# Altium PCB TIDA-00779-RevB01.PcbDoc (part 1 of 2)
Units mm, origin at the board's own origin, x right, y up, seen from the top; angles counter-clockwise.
Board outline 215 x 145 mm, 2 copper layers (Top Layer, Bottom Layer), stack 1.575 mm thick; 136 components, 56 nets, 280 pads, 32 vias.
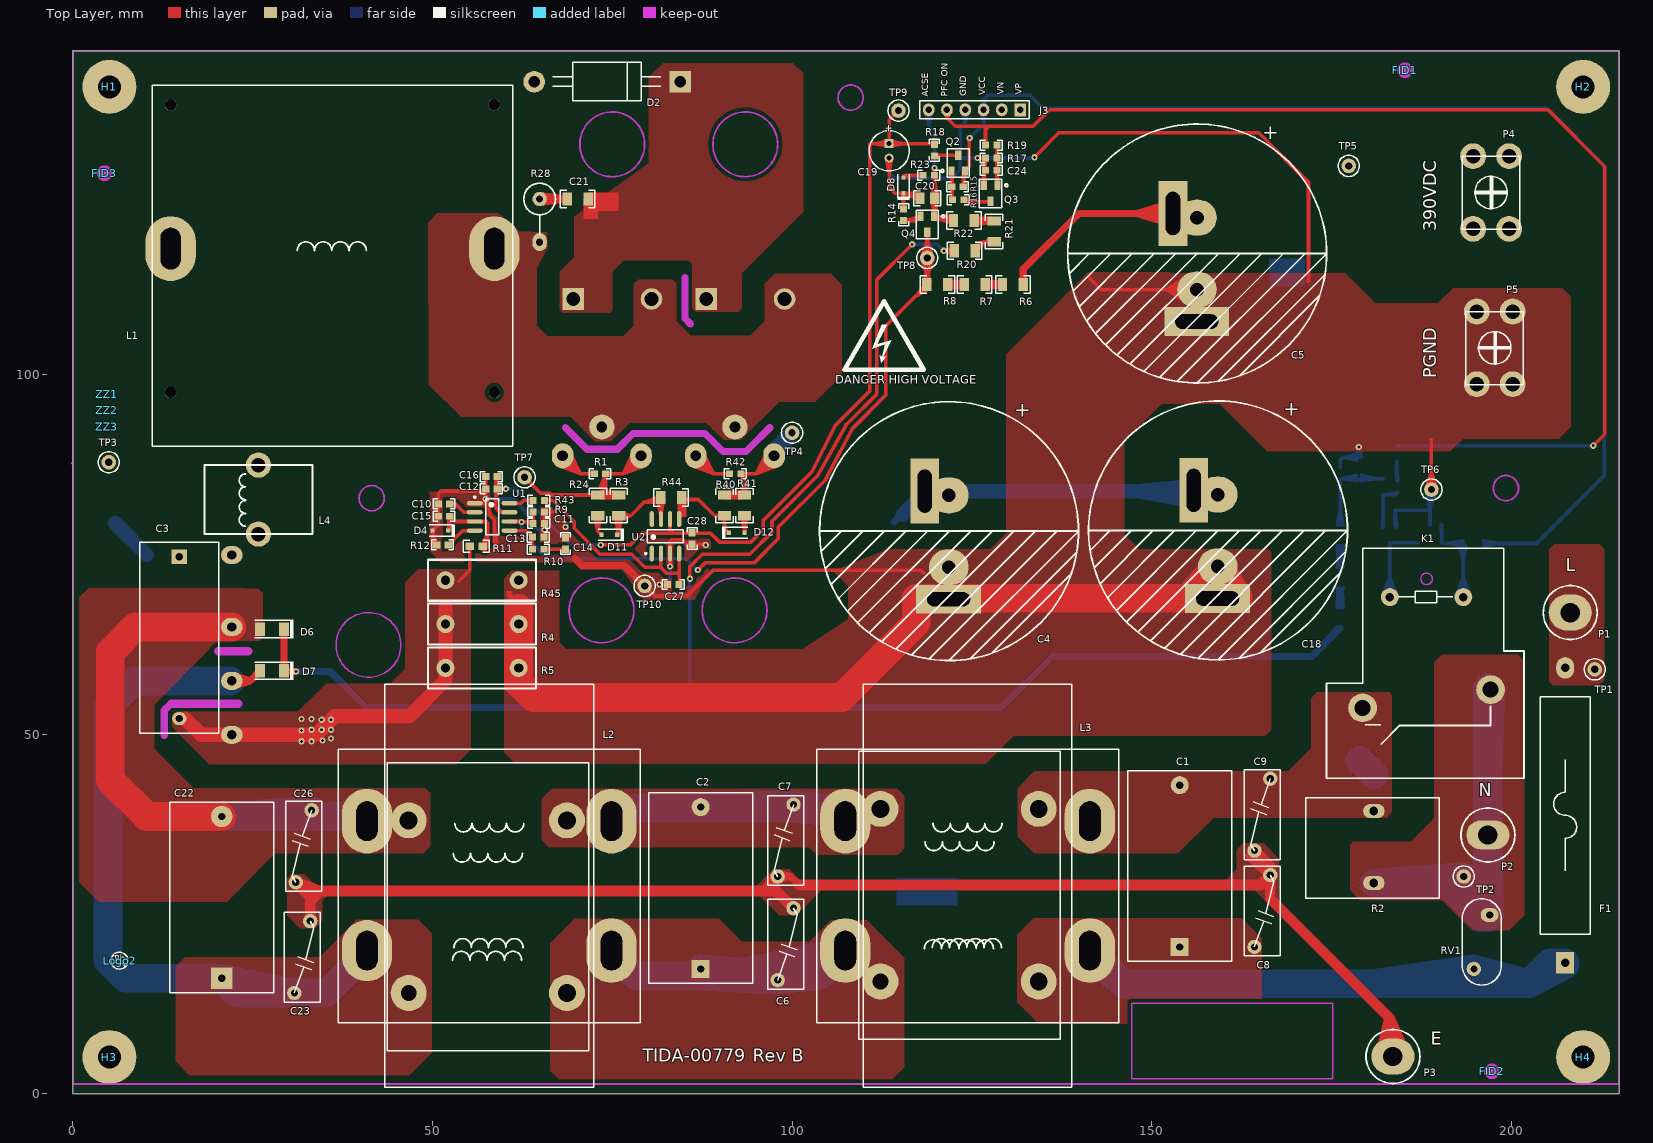
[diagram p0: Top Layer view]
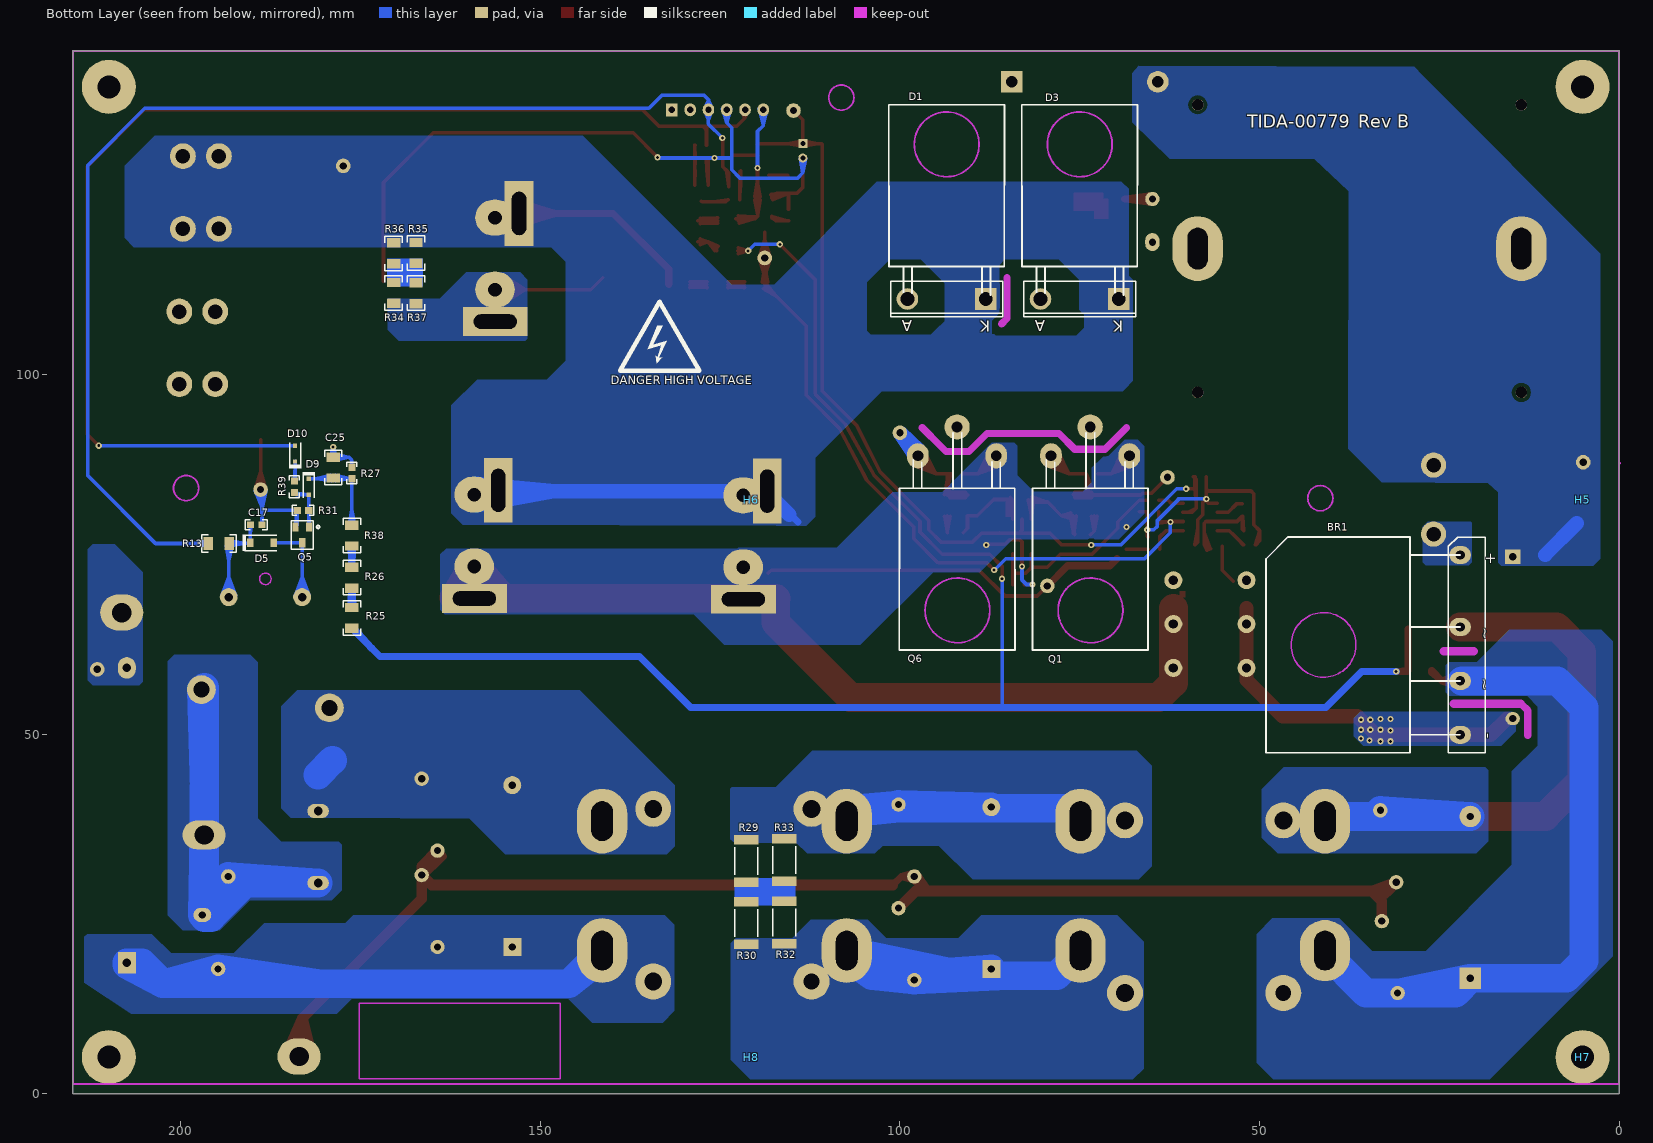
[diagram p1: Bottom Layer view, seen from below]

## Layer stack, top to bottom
Top Solder: solder mask 0.0102, Solder Resist, Dk 3.5
Top Layer: signal copper 0.0356
Dielectric1: core 1.5037, FR-4, Dk 4.8
Bottom Layer: signal copper 0.0356
Bottom Solder: solder mask 0.0102, Solder Resist, Dk 3.5

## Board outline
0,0 215,0 215,145 0,145

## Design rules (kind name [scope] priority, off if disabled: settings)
AcuteAngle [All] p1: minimum=4.50000000000000E+0001 checktracksonly=FALSE
AssemblyTestPointUsage [All] p1: valid=2
Clearance Clearance_BoardEdge_MountingHoles [OnCopper and InComponentClass('Mounting Holes') vs IsKeepOut] p1: gap=0.3
Clearance Clearance_BoardEdge_Poly [OnCopper and InPoly vs IsKeepOut] p2 off: gap=0.25
Clearance Clearance_BoardEdge [OnCopper and Not InComponentClass('Logo') and not InComponentClass('FiducialMark') and not InRegion(1000,500,4000,800) and Not IsKeepout vs IsKeepOut] p3 off: gap=1.905
Clearance Clearance_Poly [InPolygon] p4: gap=0.5
Clearance [All] p5: gap=0.25
ComponentClearance ComponentClearance_MountingHoles_FiducialMarks [InComponentClass('Mounting Holes') vs InComponentClass('FiducialMark')] p1 off: gap=1.27 collisioncheckmode=3 verticalgap=0.254 showdistances=FALSE
ComponentClearance ComponentClearance_Shunt [InComponentClass('Header') vs InComponentClass('Shunt')] p2 off: gap=0 collisioncheckmode=3 verticalgap=0 showdistances=FALSE
ComponentClearance ComponentClearance_Logo [InComponentClass('Logo')] p3 off: gap=1.27 collisioncheckmode=3 verticalgap=0.254 showdistances=FALSE
ComponentClearance ComponentClearance_ScrewToNut [(HasFootprint('NY PMS 440 0025 PH')) vs (HasFootprint('Keystone_1902C'))] p4 off: gap=0.127 collisioncheckmode=3 verticalgap=0.254 showdistances=FALSE
ComponentClearance ComponentClearance_MountingHoles [InComponentClass('Mounting Holes')] p5 off: gap=6.35 collisioncheckmode=3 verticalgap=2540 showdistances=FALSE
ComponentClearance ComponentClearance_SmallPassives [HasFootprint('0201*') or HasFootprint('0402*') or HasFootprint('0508') or HasFootprint('0603*') or HasFootprint('0612') or HasFootprint('0805*') or HasFootprint('0815*') or HasFootprint('0830*') or HasFootprint('1206*') or HasFootprint('1210*') or HasFootprint('1808*') or HasFootprint('1812*') or HasFootprint('1825*') or HasFootprint('2010*') or HasFootprint('2220*') or HasFootprint('2225*') or HasFootprint('2512*') or HasFootprint('2728*') or HasFootprint('3518*') vs HasFootprint('0201*') or HasFootprint('0402*') or HasFootprint('0508') or HasFootprint('0603*') or HasFootprint('0612') or HasFootprint('0805*') or HasFootprint('0815*') or HasFootprint('0830*') or HasFootprint('1206*') or HasFootprint('1210*') or HasFootprint('1808*') or HasFootprint('1812*') or HasFootprint('1825*') or HasFootprint('2010*') or HasFootprint('2220*') or HasFootprint('2225*') or HasFootprint('2512*') or HasFootprint('2728*') or HasFootprint('3518*')] p6 off: gap=0.508 collisioncheckmode=3 verticalgap=0.254 showdistances=FALSE
ComponentClearance ComponentClearance_THtoSMT [IsThruComponent vs IsSMTComponent] p7 off: gap=2.54 collisioncheckmode=3 verticalgap=0.762 showdistances=FALSE
ComponentClearance ComponentClearance_THtoTH [IsThruComponent vs IsThruComponent] p8 off: gap=3 collisioncheckmode=3 verticalgap=0.762 showdistances=FALSE
ComponentClearance [All] p9 off: gap=1.016 collisioncheckmode=3 verticalgap=0.254 showdistances=FALSE
DiffPairsRouting [All] p1: maxlimit=2.54 minlimit=0.254 mostfreqgap=0.254 toplayer_minwidth=0.381 toplayer_maxwidth=0.381 toplayer_prefwidth=0.381 bottomlayer_minwidth=0.381 bottomlayer_maxwidth=0.381 bottomlayer_prefwidth=0.381 maxuncoupledlength=25.4
FabricationTestPointUsage TestPointUsage [All] p1: valid=2 allowmultiple=FALSE
FabricationTestpoint Testpoint [All] p1: side=3 testpointundercomponent=TRUE minsize=1.016 maxsize=2.54 preferedsize=1.524 minholesize=0 maxholesize=1.016 preferedholesize=0.813 testpointgrid=0.025 allowsidetop=TRUE allowsidebottom=TRUE usegrid=TRUE gridtolerance=0
FanoutControl Fanout_LCC [IsLCC] p1: bgadir=Out bgaviamode=Centered fanoutstyle=Auto fanoutdirection=Alternating viagrid=0.025 // Fanout_LCC (Default Rule)
FanoutControl Fanout_BGA [IsBGA] p2: bgadir=Out bgaviamode=Centered fanoutstyle=Auto fanoutdirection=Alternating viagrid=0.025 // Fanout_BGA (Default Rule)
FanoutControl Fanout_Default [All] p4: bgadir=Out bgaviamode=Centered fanoutstyle=Auto fanoutdirection=Alternating viagrid=0.025 // Fanout_Default (Default Rule)
FanoutControl Fanout_Small [(CompPinCount < 5)] p5: bgadir=Out bgaviamode=Centered fanoutstyle=Auto fanoutdirection=OutThenIn viagrid=0.025 // Fanout_Small (Default Rule)
HoleSize [All] p1: absolutevalues=TRUE maxlimit=6.375 minlimit=0.203 maxpercent=80.000 minpercent=20.000
MinimumAnnularRing MinimumAnnularRing_ThermalPadVias [IsVia and InAnyComponent] p1: minimumring=0.15
MinimumAnnularRing [All] p2: minimumring=0.229
MinimumSolderMaskSliver MinimumSolderMaskSliver_Logo [InComponentClass('Logo') vs InComponentClass('Logo')] p1: minsoldermaskwidth=0.018
MinimumSolderMaskSliver [All] p2: minsoldermaskwidth=0.1
PlaneConnect [All] p1: planeconnectstyle=Relief reliefexpansion=0.254 reliefentries=4 reliefconductorwidth=0.254 reliefairgap=0.254
PolygonConnect [All] p1: connectstyle=Direct reliefconductorwidth=0.254 reliefentries=4 polygonreliefangle="90 Angle" airgapwidth=0.254
RoutingVias ThermalPadVias [IsVia and InAnyComponent] p1: holewidth=0.2 width=0.5 viastyle="Through Hole" minholewidth=0.2 minwidth=0.5 maxholewidth=0.33 maxwidth=0.6
RoutingVias [All] p2: holewidth=0.406 width=0.864 viastyle="Through Hole" minholewidth=0.2 minwidth=0.66 maxholewidth=1.016 maxwidth=1.651
SilkToSilkClearance SilkToSilkClearance_Pb-FreeLogo [(HasFootprint('Pb-Free_Overlay_Medium') OR HasFootprint('Pb-Free_Overlay_Small')) vs (HasFootprint('Pb-Free_Overlay_Medium') OR HasFootprint('Pb-Free_Overlay_Small'))] p1: silktosilkclearance=0
SilkToSilkClearance [All] p2: silktosilkclearance=0.102
SilkToSolderMaskClearance "Silk to Solder Mask Opening" [IsPad] p1: minsilkscreentomaskgap=0.102 clearancetoexposedcopper=TRUE
SolderMaskExpansion [All] p1: expansion=0.05
UnpouredPolygon [All] p1: allowunpoured=FALSE
Width [All] p1: maxlimit=10 minlimit=0.152 preferedwidth=0.254 checkconnectedcopper=TRUE
15 further rules are at their usual default settings.

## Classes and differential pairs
component class TIDA-00779-RevA02: BR1 C1 C2 C3 C4 C5 C6 C7 C8 C9 C10 C11 C12 C13 C14 C15 C16 C17 C18 C19 C20 C21 C22 C23 C24 C25 C26 C27 C28 D1 D2 D3 D4 D5 D6 D7 D8 D9 D10 D11 D12 F1 HS1 K1 L1 L2 L3 P1 P2 P3 P4 P5 Q1 Q2 Q3 Q4 Q5 Q6 R1 R2 R3 R4 R5 R6 R7 R8 R9 R10 R11 R12 R13 R14 R15 R16 R17 R18 R19 R20 R21 R22 R23 R24 R25 R26 R27 R28 R29 R30 R31 R32 R33 R34 R35 R36 R37 R38 R39 R40 R41 R42 R43 R44 RV1 S1 TP1 TP2 TP3 TP4 TP5 TP6 TP7 TP8 TP9 TP10 U1 U2

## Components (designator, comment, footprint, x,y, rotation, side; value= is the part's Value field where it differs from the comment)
BR1 "GBJ3508" BRIDGE-GBJ1510-BV 22.1,62.4 r270 bottom
C1 "B32923C3225K" B32923_29.5mm#1 153.9,31.65 r90 top
C2 "B32923C3225K" B32923_29.5mm#1 87.3,28.6 r90 top
C3 "B32923C3474K" B32923_20.5mm 14.8,63.4 r270 top
C4 "LGG2W681MELC50" E/P10/D36/E2 120.125,76.269 r0 top
C5 "LGG2W681MELC50" E/P10/D36/E2 154.625,114.869 r0 top
C6 "2.2nF" C/10/12/5 99.1,20.8 r90 top
C7 "2.2nF" C/10/12/5 99.1,35.2 r270 top
C8 "2.2nF" C/10/12/5 165.4,25.4 r90 top
C9 "2.2nF" C/10/12/5 165.4,38.8 r270 top
C10 "GRM188R71H472KA01D" 0603 51.6,82 r180 top
C11 "C0603C821K5RACTU" 0603 64.8,79.3 r0 top
C12 "C0603C105K3RACTU" 0603 58.2,84.1 r180 top
C13 "C0603C394K4RACTU" 0603 64.7,77.4 r0 top
C14 "0603ZD475KAT2A" 0603 68.5,76.5 r90 top
C15 "06031C272JAT2A" 0603 51.6,80.3 r180 top
C16 "0603YC104JAT2A" 0603 58.2,85.8 r180 top
C17 "C1608X7R1E105K080AB" 0603 189.5,79.1 r180 bottom
C18 "LGG2W681MELC50" E/P10/D36/E2 157.525,76.369 r0 top
C19 "UPW1V100MDD6" PW_500x700 113.5,131.1 r270 top
C20 "C2012X5R1E106K125AB" 0805_HV 118.816,124.5 r180 top
C21 "1206AC102KAT1A" 1206 70.2,124.4 r180 top
C22 "B32923C3225K" B32923_29.5mm#2 20.7,27.3 r90 top
C23 "2.2nF" C/10/12/5 31.9,19 r90 top
C24 "C0603C474K4RACTU" 0603 127.7,128.4 r180 top
C25 "UMK316BBJ106ML-T" 1206 178.8,87.05 r90 bottom
C26 "2.2nF" C/10/12/5 32.1,34.4 r270 top
C27 "C1608X7R1H221K" 0603 83.5,70.8 r180 top
C28 "UMK107AB7105KA-T" 0603 86.1,77.2 r90 top
D1 "FFH30S60S" TO247BV-D 93.5,110.5 r0 bottom
D2 "1N5406" DO-201AD 74.3,140.7 r180 top
D3 "FFH30S60S" TO247BV-D 75,110.5 r0 bottom
D4 "BAT54HT1G" sod-323 51.1,78.3 r180 top
D5 "1N4148W-7-F" SOD-123 188.7,76.6 r180 bottom
D6 "CGRM4007-G" MINI-SMA 27.7,64.6 r180 top
D7 "CGRM4007-G" MINI-SMA 27.7,58.8 r180 top
D8 "BAT54HT1G" sod-323 115.5,126.3 r90 top
D9 "BZX384-C12,115" sod-323 182.2,84.4 r270 bottom
D10 "BAT54HT1G" sod-323 184.1,89 r90 bottom
D11 "MMDL914-TP" sod-323 74.6,77.7 r180 top
D12 "MMDL914-TP" sod-323 92.3,78 r0 top
"DANGER HIGH VOLTAGE" "Comment" IEC_HighVoltage_Medium 112.8,105.1 r0 top
"DANGER HIGH VOLTAGE" "Comment" IEC_HighVoltage_Medium 133.4,105 r180 bottom
F1 "40A" Fuse-6*32 207.5,38.7 r270 top
FID1 "Fiducial" Fiducial10-20 185.2,142.3 r0 top
FID2 "Fiducial" Fiducial10-20 197.3,3.1 r0 top
FID3 "Fiducial" Fiducial10-20 4.4,128 r0 top
H1 "NY PMS 440 0025 PH" "NY PMS 440 0025 PH"#1 5.08,82.55 r0 top locked
H2 "NY PMS 440 0025 PH" "NY PMS 440 0025 PH"#2 120.65,82.55 r0 top locked
H3 "NY PMS 440 0025 PH" "NY PMS 440 0025 PH"#3 5.08,5.08 r0 top locked
H4 "NY PMS 440 0025 PH" "NY PMS 440 0025 PH"#4 120.65,5.08 r0 top locked
H5 "1902C" Keystone_1902C 5.08,82.55 r180 bottom locked
H6 "1902C" Keystone_1902C 120.65,82.55 r180 bottom locked
H7 "1902C" Keystone_1902C 5.08,5.08 r180 bottom locked
H8 "1902C" Keystone_1902C 120.65,5.08 r180 bottom locked
J3 "PEC06SAAN" HDR1X6 131.7,136.8 r180 top
K1 "HF105F-1/12DT-1HS" RY-SLA-S112DM 185.9,56.8 r180 top (schematic designator RY1)
L1 "" L4p-55*50P40*45 36.1,117.5 r270 top
L2 "2.5 mH" L4P-56*42P42*38-LT38-4P#1 57.9,28.9 r90 top
L3 "2.5 mH" L4P-56*42P42*38-LT38-4P#2 124.4,28.9 r90 top
L4 "" L-15*9 25.8,82.6 r90 top
Logo2 "Pb-Free Symbol" Pb-Free_Overlay_Small 6.5,18.5 r0 top
P1 "" P-CONNECT#1 208.551,66.725 r0 top
P2 "" P-CONNECT#2 197.1,35.8 r0 top
P3 "" P-CONNECT#1 183.9,5 r0 top
P4 "PCB-7(M4)" PCB-7(M4) 197.2,125.3 r270 top (schematic designator P8)
P5 "PCB-7(M4)" PCB-7(M4) 197.7,103.7 r270 top (schematic designator P8)
Q1 "IPW60R099P6" TO-247BV2 73.5,67.2 r0 bottom
Q2 "MMBT3906" SOT23-3p 123.1,129.4 r0 top
Q3 "2N7002-7-F" SOT23-3p 127.6,125.2 r180 top
Q4 "BC847CLT1G" SOT23-3p 118.8,120.9 r180 top
Q5 "2N7002-7-F" SOT23-3p 183.1,77.7 r0 bottom
Q6 "IPW60R099P6" TO-247BV2 92,67.2 r0 bottom
R1 "CRCW060310K0FKEA" 0603 73.3,86.2 r180 top
R2 "B470N" PTC-18*13P10 180.9,34.3 r180 top
R3 "CRCW120622R0JNEA" 1206 75.9,81.8 r90 top
R4 "" R/P10/5W 56.9,65.3 r180 top
R5 "" R/P10/5W 56.9,59.2 r180 top
R6 "CRCW1206332KFKEA" 1206 130.7,112.5 r0 top
R7 "CRCW1206332KFKEA" 1206 125.4,112.5 r0 top
R8 "CRCW1206340KFKEA" 1206 120.2,112.5 r0 top
R9 "CRCW060313K0FKEA" 0603 64.8,80.9 r180 top
R10 "RT0603DRE0718K7L" 0603 64.7,75.7 r0 top
R11 "CRCW0603221RFKEA" 0603M 56.1,76.1 r0 top
R12 "RT0603DRE0747KL" 0603 51.4,76.3 r0 top
R13 "CRCW1206100RFKEA" 1206 194.7,76.5 r180 bottom
R14 "CRCW060313K7FKEA" 0603 115.5,122.2 r90 top
R15 "CRCW060310K0FKEA" 0603 123,126.1 r180 top
R16 "CRCW06036K80JNEA" 0603 123.1,124.3 r180 top
R17 "CRCW06036K80JNEA" 0603 127.7,130.1 r0 top
R18 "CRCW060315R4FKEA" 0603 119.8,131.2 r90 top
R19 "CRCW060310K0FKEA" 0603 127.7,131.9 r0 top
R20 "CRCW1206332KFKEA" 1206 124,117.2 r180 top
R21 "CRCW1206332KFKEA" 1206 128.1,119.9 r90 top
R22 "CRCW1206340KFKEA" 1206 123.9,121.4 r0 top
R23 "CRCW060310K0FKEA" 0603 119,127.7 r180 top
R24 "CRCW12064R70JNEA" 1206 73,81.8 r90 top
R25 "CRCW1206340KFKEA" 1206 176.2,66.15 r270 bottom
R26 "CRCW1206340KFKEA" 1206 176.2,71.75 r90 bottom
R27 "CRCW0603221KFKEA" 0603 176.2,86.3 r270 bottom
R28 "CRM2512-FX-43R2ELF" R5/D4.4V 64.9,124.4 r270 top
R29 "CRCW251262K0JNEG" 2512 121.4,32.35 r270 bottom
R30 "CRCW251262K0JNEG" 2512 121.4,23.75 r270 bottom
R31 "CRCW060347K5FKEA" 0603 183,81.1 r180 bottom
R32 "CRCW251262K0JNEG" 2512 116.1,23.8 r270 bottom
R33 "CRCW251262K0JNEG" 2512 116.1,32.5 r270 bottom
R34 "CRCW1206221KFKEA" 1206 170.4,111.35 r90 bottom
R35 "CRCW1206221KFKEA" 1206 167.3,116.9 r90 bottom
R36 "CRCW1206221KFKEA" 1206 170.4,116.85 r90 bottom
R37 "CRCW1206221KFKEA" 1206 167.3,111.3 r90 bottom
R38 "CRCW120621K0FKEA" 1206 176.2,77.6 r90 bottom
R39 "CRCW06031K00FKEA" 0603 184.2,84.4 r270 bottom
R40 "CRCW120622R0JNEA" 1206 90.6,81.8 r90 top
R41 "CRCW12064R70JNEA" 1206 93.4,81.8 r90 top
R42 "CRCW060310K0FKEA" 0603 92.1,86.2 r180 top
R43 "RT0603DRE07100RL" 0603 64.8,82.5 r0 top
R44 "RC1206JR-070RL" 1206 83.2,82.9 r0 top
R45 "" R/P10/5W 56.9,71.4 r180 top (schematic designator R4)
RV1 "S10K275E2" VAR_S10K275E2 195.9,21.1 r270 top
TP1 "5000" Keystone5000 211.6,59 r0 top
TP2 "5000" Keystone5000 193.4,30.2 r0 top
TP3 "5000" Keystone5000 5,87.8 r0 top
TP4 "5000" Keystone5000 100,91.9 r0 top
TP5 "5000" Keystone5000 177.4,129 r0 top
TP6 "5001" Keystone5001 188.9,84 r0 top
TP7 "5000" Keystone5000 62.8,85.7 r0 top
TP8 "5000" Keystone5000 118.8,116.2 r0 top
TP9 "5000" Keystone5000 114.8,136.7 r0 top
TP10 "5001" Keystone5001 79.5,70.6 r0 top
U1 "UCC28180D" D0008A_N 58.3,80.2 r0 top
U2 "UCC27524AD" D0008A_N 82.4,77.5 r90 top
ZZ1 "These assemblies are ESD sensitive, ESD precautions shall be observed." AssemblyNote 4.699,97.259 r0 top
ZZ2 "These assemblies must be clean and free from flux and all contaminants. Use of no clean flux is not acceptable." AssemblyNote 4.699,95.01 r0 top
ZZ3 "These assemblies must comply with workmanship standards IPC-A-610 Class 2, unless otherwise specified." AssemblyNote 4.699,92.761 r0 top
? "Comment" "L4p-32*28 P22*24" 123.3,27.6 r90 top
? "Comment" "L4p-32*28 P22*24" 57.7,26 r90 top

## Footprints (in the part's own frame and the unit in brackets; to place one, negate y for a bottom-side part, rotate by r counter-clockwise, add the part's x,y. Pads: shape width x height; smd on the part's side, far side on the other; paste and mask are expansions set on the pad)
0603 [mm] "0603 from SM-752 data"
  rect 1x0.95 smd: 1(-0.8,0) 2(0.8,0)
  silkscreen extent -1.52,-0.69 1.52,0.69, body extent -0.87,-0.47 0.87,0.47, height 0.85
0603M [mm] "0603 from SM-752 data"
  rect 1.2x1.05 smd: 1(-0.9,0) 2(0.9,0)
  silkscreen extent -1.82,-0.84 1.82,0.84, body extent -0.87,-0.47 0.87,0.47, height 0.85
0805_HV [mil] "0805 with 30mil clearance between pads"
  rect 50x63 smd: 1(-40,0) 2(40,0)
  silkscreen extent -74,-40 74,40, body extent -43,-29 43,29, height 57
1206 [mm] "1206 from SM-752 data"
  rect 1.3x1.85 smd: 1(-1.45,0) 2(1.45,0)
  silkscreen extent -2.4,-1.21 2.4,1.21, body extent -1.7,-0.9 1.7,0.9, height 1.35
2512 [mm] "Chip Resistor, Body 6.3x3.2mm, IPC Medium Density"
  rect 1.3x3.4 smd: 1(-2.95,0) 2(2.95,0)
  silkscreen extent -1.9,-1.6 1.9,1.6, body extent -3.22,-1.67 3.22,1.67, height 0.71
AssemblyNote [mm] "Assembly Note"
B32923_20.5mm [mm] "Epcos film capacitors, 22.5mm spacing"
  rect 2x2.2 hole 1: 1(-11.25,0)
  oval 1.8x2 hole 1: 2(11.25,0)
  silkscreen extent -13.25,-5.5 13.25,5.5, body extent -13.25,-5.5 13.25,5.5, height 20.5
B32923_29.5mm#1 [mm] "Epcos film capacitors, 22.5mm spacing"
  rect 2.5x2.5 hole 1: 1(-11.25,0)
  round 2.5 hole 1: 2(11.25,0)
  silkscreen extent -13.25,-7.25 13.25,7.25, body extent -13.25,-7.25 13.25,7.25, height 29.5
B32923_29.5mm#2 [mm] "Epcos film capacitors, 22.5mm spacing"
  rect 3x3 hole 1: 1(-11.25,0)
  round 3 hole 1: 2(11.25,0)
  silkscreen extent -13.25,-7.25 13.25,7.25, body extent -13.25,-7.25 13.25,7.25, height 29.5
BRIDGE-GBJ1510-BV [mm]
  oval 2.5x3 hole 1.3: 1(-12.5,0) 2(-2.5,0) 3(5,0) 4(12.5,0)
  Keep-Out Layer circle w0.2: c0,-19 r4.5
  silkscreen extent -15,-27 15,3.5
C/10/12/5 [mm]
  round 2 hole 1: 1(-5,1.1) 2(5,-1.1)
  silkscreen extent -6.25,-2.5 6.25,2.5
D0008A_N [mm] "SOIC, 8-Leads, Body 4.9x3.9mm, Pitch 1.27mm, IPC Medium Density"
  oval 2.2x0.6 smd: 1(-2.4,1.905) 2(-2.4,0.635) 3(-2.4,-0.635) 4(-2.4,-1.905) 5(2.4,-1.905) 6(2.4,-0.635) 7(2.4,0.635) 8(2.4,1.905)
  silkscreen extent -2.52,-2.5 0.9,2.88, body extent -2,-2.5 2,2.5, height 1.75
DO-201AD [mm] "Vishay dimensions"
  rect 3x3 hole 1.6: 1(-10.16,0)
  round 3 hole 1.6: 2(10.16,0)
  silkscreen extent -7.47,-2.7 7.57,2.61, body extent -10.82,-2.74 10.82,2.61, height 5.33
E/P10/D36/E2 [mm]
  rect 4x9 hole 2 slot 6 at 90 deg: 1(-1.675,7.519)
  oval 5.5x5 hole 1.9: 1(1.675,6.931) 2(1.675,-3.069)
  rect 9x4 hole 2 slot 6 at 0 deg: 2(1.641,-7.519)
  silkscreen extent -16.29,-16.05 19.7,19.95
Fiducial10-20 [mm]
  round 1 smd mask+0.5: 1(0,0)
  Top Layer keep-out circle w1.178: c0,0 r0.5
Fuse-6*32 [mm]
  rect 3x2.5 hole 1.2: 1(20.5,0)
  oval 3x2.5 hole 1.2: 2(-20.5,0)
  silkscreen extent -16.5,-3.5 16.5,3.5
HDR1X6 [mm] "Connector; Header; 6 Position"
  rect 1.6x1.8 hole 0.9: 1(0,0)
  oval 1.6x1.8 hole 0.9: 2(2.54,0) 3(5.08,0) 4(7.62,0) 5(10.16,0) 6(12.7,0)
  silkscreen extent -1.27,-1.27 13.97,1.27
IEC_HighVoltage_Medium [mm]
  silkscreen extent -5.51,-4.46 5.51,5.09
Keystone5000 [mil] "For Keystone 500x miniature loop terminals"
  round 80 hole 40: 1(0,0)
  silkscreen extent -58,-58 58,58, body extent -49,-49 49,49, height 182
Keystone5001 [mil] "For Keystone 500x miniature loop terminals"
  round 80 hole 40: 1(0,0)
  silkscreen extent -58,-58 58,58, body extent -49,-49 49,49, height 182
Keystone_1902C [mm] "Hex Standoff, 4-40 threaded, nylon"
  body extent -3.68,-3.2 3.71,3.2, height 12.73
"L4p-32*28 P22*24" [mm]
  round 5 hole 2.5: 1(-12,-11) 3(12,11) 4(12,-11)
  round 5 hole 2.2: 2(-12,11)
  silkscreen extent -20,-14 20,14
L4p-55*50P40*45 [mm]
  oval 9x7 hole 2.8 slot 5.8 at 0 deg: 1(0,-22.5) 2(0,22.5)
  round 1.6 hole 1.6 unplated: 3(-20,22.5) 3(-20,-22.5) 3(20,22.5) 3(20,-22.5)
  silkscreen extent -22.75,-25.05 27.5,25.05
L4P-56*42P42*38-LT38-4P#1 [mm]
  oval 9x7 hole 3 slot 5.5 at 0 deg: 1(-9,-17) 3(9,17) 4(9,-17)
  oval 8.5x7 hole 3 slot 5.5 at 0 deg: 2(-9,17)
  silkscreen extent -28,-21 28,21
L4P-56*42P42*38-LT38-4P#2 [mm]
  oval 9x7 hole 3 slot 5.5 at 0 deg: 1(-9,-17) 2(-9,17) 3(9,17) 4(9,-17)
  silkscreen extent -28,-21 28,21
L-15*9 [mm]
  round 3.5 hole 2: 1(-4.8,0) 2(4.8,0)
  silkscreen extent -4.8,-7.5 4.8,7.5
MINI-SMA [mm] "COMCHIP"
  rect 1.4x1.9 smd: 1(-1.65,0) 2(1.65,0)
  silkscreen extent -3,-1.3 2.4,1.3, body extent -1.95,-0.9 1.95,0.9, height 1.7
"NY PMS 440 0025 PH"#1 [mm] "4-40 nylon screw and mounting hole"
  round 7.5 hole 3.2: 1(0,57.45)
  body extent -3.3,-3.3 3.3,3.3, height 2.69
"NY PMS 440 0025 PH"#2 [mm] "4-40 nylon screw and mounting hole"
  round 7.5 hole 3.2: 1(89.35,57.45)
  body extent -3.3,-3.3 3.3,3.3, height 2.69
"NY PMS 440 0025 PH"#3 [mm] "4-40 nylon screw and mounting hole"
  round 7.5 hole 3.2: 1(0,0)
  body extent -3.3,-3.3 3.3,3.3, height 2.69
"NY PMS 440 0025 PH"#4 [mm] "4-40 nylon screw and mounting hole"
  round 7.5 hole 3.2: 1(89.35,0)
  body extent -3.3,-3.3 3.3,3.3, height 2.69
P-CONNECT#1 [mm]
  oval 6x5 hole 2.7: 1(-0.351,0.175)
  silkscreen extent -4.1,-3.57 3.4,3.92
P-CONNECT#2 [mm]
  oval 6x4 hole 2.7: 1(-0.351,0.175)
  silkscreen extent -4.1,-3.57 3.4,3.92
Pb-Free_Overlay_Small [mm]
  silkscreen extent -1.16,-1.17 1.17,1.17
PCB-7(M4) [mm]
  round 3.6 hole 2: 1(-5.05,-2.5) 2(5.05,-2.5) 3(5.05,2.5) 4(-5.05,2.5)
  silkscreen extent -5.05,-4 5.11,4
PTC-18*13P10 [mm]
  oval 3x2 hole 1.2: 1(0,5) 2(0,-5)
  silkscreen extent -9.05,-6.85 9.45,7.15
PW_500x700 [mm] "Nichicon"
  rect 1.25x1.25 hole 0.711: 1(-1,0)
  round 1.25 hole 0.711: 2(1,0)
  silkscreen extent -2.8,-2.8 2.8,2.8, body extent -2.73,-2.75 2.75,2.75, height 8.01
R5/D4.4V [mm]
  oval 2.5x2 hole 1: 1(6,0)
  round 2 hole 1: 2(0,0)
  silkscreen extent -2.2,-2.2 5,2.2
R/P10/5W [mm]
  round 2.5 hole 1.3: 1(-5.08,0) 2(5.08,0)
  silkscreen extent -7.5,-2.85 7.5,2.85
RY-SLA-S112DM [mm]
  round 2.5 hole 1.2: 1(-7.427,-12.25) 2(2.773,-12.25)
  round 4 hole 2.2: 3(-11.227,0.61) 4(6.573,3.15)
  Keep-Out Layer circle w0.2: c-2.324,-14.783 r0.8
  silkscreen extent -15.88,-19.02 11.58,12.93
SOD-123 [mm] "On Semi recommended land pattern"
  rect 0.915x1.22 smd: 1(-1.637,0) 2(1.637,0)
  silkscreen extent -2.74,-1.17 2.03,1.17, body extent -1.93,-0.9 1.93,0.9, height 1.35
sod-323 [mm] "NXP recommended land pattern"
  rect 0.6x0.6 smd paste-0.05: 1(-1.1,0) 2(1.1,0)
  silkscreen extent -2.06,-0.86 1.53,0.86, body extent -1.3,-0.67 1.3,0.68, height 1.1
SOT23-3p [mm]
  rect 0.85x1.3 smd: 1(-0.953,-1.1) 2(0.953,-1.1) 3(0,1.1)
  silkscreen extent -2.4,-1.95 1.55,2
TO247BV-D [mm]
  round 3 hole 1.9: 1(5.458,0.006)
  rect 3x3 hole 1.9: 2(-5.442,0.006)
  Keep-Out Layer circle w0.254: c0,-21.5 r4.5
  silkscreen extent -8.02,-26.99 8.05,2.51
TO-247BV2 [mm]
  oval 3x3.5 hole 1.5: 1(5.5,-21.5) 3(-5.4,-21.5)
  round 3.5 hole 1.5: 2(0.05,-25.5)
  Keep-Out Layer circle w0.254: c0,0 r4.5
  silkscreen extent -7.99,-24.7 8.08,5.5
VAR_S10K275E2 [mm] "EPCOS"
  oval 2x2.5 hole 1: 1(-3.75,1.1)
  round 2 hole 1: 2(3.75,-1.1)
  silkscreen extent -6,-2.7 6,2.7, body extent -5.98,-2.7 5.98,2.7, height 14.99

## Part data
BR1: library part D-BRIDGE_GBJ_15A_SERIES, "Diode, Bridge Rectifier, GPP 35A 800V GBJ"
C1 C2 C22: "CAP, Film, 2.2 μF, 630 V, +/- 10%, TH"
C3: library part B32923C3105K, "CAP, Film, 1 礔, 630 V, +/- 10%, 0.018 ohm, TH"
C4 C5 C18: library part 450QXW220MEFC18X50, "CAP, ALUMINIUM, RADIAL, 680 uF, 450 V, 20%, TH"
C6 C7 C8 C9 C23 C26: library part CS11-E2GA222MYNS, "CAP CER 2200PF 400VAC 20% RADIAL DISC 10mm Dia"
C10: "CAP, CERM, 4700 pF, 50 V, +/- 10%, X7R, 0603"
C11: "CAP, CERM, 820 pF, 50 V, +/- 10%, X7R, 0603"
C12: "CAP, CERM, 1 μF, 25 V, +/- 10%, X7R, 0603_095"
C13: "CAP, CERM, 0.39 μF, 16 V, +/- 10%, X7R, 0603"
C14: "CAP, CERM, 4.7 μF, 10 V, +/- 10%, X5R, 0603"
C15: "CAP, CERM, 2700 pF, 100 V, +/- 5%, X7R, 0603"
C16: "CAP, CERM, 0.1 μF, 16 V, +/- 5%, X7R, 0603"
C17: "CAP, CERM, 1 礔, 25 V, +/- 10%, X7R, 0603"
C19: "CAP, AL, 10uF, 35V, +/-20%, 0.95 ohm, TH"
C20: "CAP, CERM, 10 礔, 25 V, +/- 10%, X5R, 0805"
C21: library part GRM31A7U3A331JW31D, "CAP, CERM, 1000 pF, 1000 V, +/- 5%, X7R, 1206"
C24: "CAP, CERM, 0.47 μF, 16 V, +/- 10%, X7R, 0603"
C25: library part GRM319R61H475KA12, "CAP CER 10UF 50V 20% X5R 1206"
C27: "CAP, CERM, 220 pF, 50 V, +/- 10%, X7R, 0603"
C28: "CAP, CERM, 1 μF, 50 V, +/- 10%, X7R, 0603"
D1 D3: library part C3D04060A, "Diode, 600 V, 30 A, TH"
D2: "Diode, Switching-Bridge, 600 V, 3 A, TH"
D4 D8 D10: "Diode, Schottky, 30V, 0.2A, SOD-323"
D5: "Diode, Ultrafast, 100V, 0.15A, SOD-123"
D6 D7: "Diode, P-N, 1000 V, 1 A, 3.9x1.7x1.8mm"
D9: "Diode, Zener, 12V, 300mW, SOD-323"
D11 D12: "Diode, Switching, 100 V, 0.2 A, SOD-323"
F1: library part 01110501Z, "FUSE CLIP, CARTRIDGE, 250V, 40A, PCB"
FID1 FID2 FID3: "Fiducial mark.  There is nothing to buy or mount."
H1 H2 H3 H4: "Machine Screw, Round, #4-40 x 1/4, Nylon, Philips panhead"
H5 H6 H7 H8: "Standoff, Hex, 0.5\"L #4-40 Nylon"
J3: "Header, 100mil, 6x1, Tin, TH"
K1: library part Relay-SPST, "Single-Pole Single-Throw Relay"
L1: library part 750342810, "INDUCTOR, 360 uH, 8.3 A, 10%, TH"
L2 L3: library part 8113-RC, "INDUCTOR, CHOKE, COMMON MODE, 2.5 mH, 30 A, 22 mOHM, TH"
L4: library part IND_74451147, "Inductor, 0.5A, 0.160 Ohm"
Logo2: library part Pb-Free
P1 P2 P3: library part CON1, "Pad"
P4 P5: library part PADS/LINE/3.0
Q1 Q6: library part IPP60R190P6, "MOSFET, N-CH, 600 V, 37.9 A, TO-247"
Q2: library part "MMBT3906, Fairchild Semiconductor", "Transistor, PNP, 40V, 0.2A, SOT-23"
Q3 Q5: "MOSFET, N-CH, 60V, 0.17A, SOT-23"
Q4: library part "BC847CLT1G, ON Semiconductor", "Transistor, NPN, 45 V, 0.1 A, SOT-23"
R1 R23 R42: "RES, 10.0 k, 1%, 0.1 W, 0603"
R2: library part "Res Adj2", "PTC, 47 ohm"
R3 R40: "RES, 22, 5%, 0.25 W, 1206"
R4 R5 R45: library part CSRN2512FKR200, "RES, 0.01, 1%, 5 W, TH"
R6 R7 R20 R21: "RES, 332 k, 1%, 0.25 W, 1206"
R8 R22 R25 R26: "RES, 340 k, 1%, 0.25 W, 1206"
R9: "RES, 13.0 k, 1%, 0.1 W, 0603"
R10: "RES, 18.7 k, 0.5%, 0.1 W, 0603"
R11: "RES, 221 ohm, 1%, 0.1W, 0603"
R12: "RES, 47.0 k, 0.5%, 0.1 W, 0603"
R13: "RES, 100, 1%, 0.25 W, 1206"
R14: "RES, 13.7 k, 1%, 0.1 W, 0603"
R15 R19: "RES, 10.0k ohm, 1%, 0.1W, 0603"
R16 R17: "RES, 6.8 k, 5%, 0.1 W, 0603"
R18: "RES, 15.4, 1%, 0.1 W, 0603"
R24 R41: "RES, 4.7, 5%, 0.25 W, 1206"
R27: "RES, 221 k, 1%, 0.1 W, 0603"
R28: library part CRCW2512100RFKEG, "RES, 300K, 1%, 1 W, TH"
R29 R30 R32 R33: "RES, 62 k, 5%, 1 W, 2512"
R31: "RES, 47.5 k, 1%, 0.1 W, 0603"
R34 R35 R36 R37: "RES, 221 k, 1%, 0.25 W, 1206"
R38: "RES, 21.0 k, 1%, 0.25 W, 1206"
R39: "RES, 1.00 k, 1%, 0.1 W, 0603"
R43: "RES, 100, 0.5%, 0.1 W, 0603"
R44: "RES, 0, 5%, 0.25 W, 1206"
RV1: "Varistor 275V RMS 10MM Radial, TH"
TP1 TP2 TP3 TP4 TP5 TP7 TP8 TP9: "Test Point, Miniature, Red, TH"
TP6 TP10: "Test Point, Miniature, Black, TH"
U1: "8-PIN CONTINUOUS CONDUCTION MODE (CCM) PFC CONTROLLER, D0008A"
U2: "Dual 5-A High-Speed Low-Side Gate Driver, D0008A"
ZZ1 ZZ2 ZZ3: library part AssemblyNote

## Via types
v1: diameter 0.864, hole 0.406, Top Layer to Bottom Layer, 32 vias

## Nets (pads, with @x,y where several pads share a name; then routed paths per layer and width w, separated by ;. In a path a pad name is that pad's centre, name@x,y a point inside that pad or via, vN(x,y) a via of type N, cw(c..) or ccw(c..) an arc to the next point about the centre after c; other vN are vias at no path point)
ACSENSE: C20.1 J3.6 Q4.1 R22.1 R23.1 | length 63.9
  Top Layer w0.5: C20.1@119.449,124.7 119.832,126.8 ; C20.1@119.753,124.15 Q4.1@119.753,122.225 ; v1(119.8,128.7) R23.1@119.8,127.7 ; C20.1@119.832,124.665 119.832,126.8 ; 119.832,125.717 R23.1@119.8,127.7 ; C20.1@120.215,124.7 119.832,126.8 ; R22.1@121.913,121.65 Q4.1@119.753,122 ; R22.1@122.368,121.009 120.284,121.65 ; R22.1@122.37,121.283 120.28,121.915 ; R22.1@122.45,121.4 120.284,121.65 ; R22.1@122.45,121.675 120.28,121.915 ; R22.1@122.457,122.075 120.28,121.915 ; R22.1@122.459,121.8 120.284,121.65 ; R22.1@122.8,121.65 120.103,121.65 Q4.1@119.753,122 ; Q4.1@119.753,122 119.753,124.421 C20.1@119.832,124.5 119.832,127.268 119.8,127.3 R23.1@119.8,127.7 ; Q4.1@119.753,122.198 119.832,124.335 Q4.1@119.753,122.225 ; Q4.1@119.753,122.198 119.448,124.314 Q4.1@119.753,122.225 ; Q4.1@119.753,122.198 120.214,124.286 Q4.1@119.753,122.225
  Bottom Layer w0.5: J3.6@118.449,136.929 119.02,134.675 ; J3.6@119.591,136.929 119.02,134.675 ; v1(119.8,128.7) 119.8,133.8 119.02,134.58 119.02,137 119.02,134.675
GNDE: C6.2 C7.2 C8.2 C9.2 C23.2 C26.2 P3.1 | length 241.5
  Top Layer w1: C7.2@97.617,30.521 96,28.2 ; C7.2@98.069,29.705 99.8,30.2 ; C7.2@98.069,30.695 99.8,30.2 ; C7.2@98.321,29.817 96,28.2 ; 101,29 99.8,30.2 ; 163.5,33 C9.2@164.3,33.8 ; 96,28.2 C7.2@98,30.2 99.8,30.2
  Top Layer w1.5: C23.2@33,24 33,26.8 34,27.8 ; 101,29 165.1,29 C8.2@166.5,30.4 ; P3.1@181.804,5.316 183.1,10.5 ; P3.1@183.1,5.7 183.1,10.5 ; P3.1@183.549,5.175 183.1,10.5 ; P3.1@185.245,5.605 183.1,10.5 ; C26.2@31,29.4 32.2,28.2 ; C26.2@31,29.4 34.4,28.2 ; C26.2@31,29.4 32.2,28.2 ; 32.2,28.2 32.6,27.8 34,27.8 ; 32.2,28.2 34.4,28.2 ; 34,27.8 34.4,28.2 ; 34.4,28.2 96,28.2 97.8,28.2 ; 97.8,28.2 C6.2@100.2,25.8 97.8,28.2 ; C9.2@164.3,33.8 C8.2@166.5,30.4 ; C9.2@164.3,33.8 C8.2@166.5,30.4 ; C9.2@164.3,33.8 C8.2@166.5,30.4 ; C9.2@164.3,33.8 166.5,31.6 ; C8.2@166.5,30.4 163.9,33 C8.2@166.5,30.4 ; C8.2@166.5,30.4 166.5,31.6 ; C8.2@166.5,30.4 166.5,27.1 183.1,10.5 ; C8.2@166.5,30.4 166.5,31.6
NetBR1_1: BR1.1 L4.1
NetBR1_2: ?.3@46.7,38 BR1.2 C22.2 C26.1 D6.2 L2.3 | length 107.9
  Top Layer w4: C22.2@20.7,38.55 10.25,38.55 5.2,43.6 5.2,61.4 8.7,64.9 ; BR1.2@21.85,64.9 8.7,64.9 ; BR1.2@22.1,64.9 8.7,64.9
  Bottom Layer w4: 25.346,38.55 C26.1@33.2,39.4 C22.2@20.7,38.55 40.05,38.55 L2.3@40.9,37.7
NetBR1_3: ?.2@46.7,14 BR1.3 C22.1 C23.1 D7.2 L2.2 | length 132.4
  Top Layer w1: BR1.3@22.1,57.4 24.65,57.4 ; BR1.3@22.35,57.4 24.65,57.4 ; BR1.3@22.472,56.66 24.65,57.4 ; BR1.3@22.472,58.14 24.65,57.4 ; D7.2@26.05,58.55 24.65,57.4 ; D7.2@26.05,58.8 24.65,57.4
  Bottom Layer w4: BR1.3@20.6,57.4 8.6,57.4 ; BR1.3@21.85,57.4 8.6,57.4 ; L2.2@40.9,19.7 35.2,14 C23.1@30.8,14 ; 8.6,57.4 4.9,53.7 4.9,18.5 7.35,16.05 C22.1@20.7,16.05 ; C22.1@20.7,16.05 22.75,14 ; C22.1@20.7,16.05 C23.1@30.8,14 ; C22.1@20.7,16.05 22.75,14 ; 22.75,14 C23.1@30.8,14
NetC1_1: ?.1@134.3,15.6 C1.1 C8.1 F1.1 L3.1 RV1.2 | length 105.2
  Bottom Layer w4: L3.1@141.4,18.9 146,15.3 ; L3.1@141.4,19.9 146,15.3 ; 180.557,15.3 RV1.2@194.8,17.35 202.5,15.3 ; F1.1@207.5,17.95 202.5,15.3 ; 146,15.3 202.5,15.3 ; 202.5,15.3 205.4,18.2 ; 205.4,18.2 F1.1@207.5,18.2 205.4,18.2
NetC2_1: ?.1@68.7,14 ?.2@112.3,15.6 C2.1 C6.1 L2.1 L3.2 R30.2 R32.2 | length 130.9
  Bottom Layer w4: L2.1@74.9,19.7 78.2,16.4 103.9,16.4 ; 84.849,16.4 C6.1@98,15.8 ; 93.284,16.4 C2.1@87.3,17.35 ; C2.1@87.3,17.35 C6.1@98,15.8 ; C2.1@87.3,17.35 100.828,16.4 C6.1@98,15.8 ; C6.1@98,15.8 103.9,16.4 ; C6.1@98,15.8 90.737,16.4 L3.2@107.4,19.9 ; C6.1@98,15.8 L3.2@107.4,19.9 ; 103.9,16.4 107.4,18.9 103.9,16.4 ; 103.9,16.4 L3.2@107.4,19.9
NetC2_2: ?.3@112.3,39.6 ?.4@68.7,38 C2.2 C7.1 L2.4 L3.3 R29.1 R33.1 | length 96.7
  Bottom Layer w4: L2.4@74.9,37.7 76.9,39.7 C7.1@100.2,39.7 ; C2.2@87.091,39.7 C7.1@100.2,40.2 ; 91.058,39.7 C2.2@87.3,39.85 ; L3.3@107.4,37.9 L3.3@105.6,39.7 ; C2.2@87.3,39.85 C7.1@100.2,40.2 ; C2.2@87.3,39.85 C7.1@100.2,39.7 ; C7.1@100.2,39.7 L3.3@105.6,39.7 ; C7.1@100.2,39.7 107.4,38.9 C7.1@100.2,40.2 ; C7.1@100.2,40.2 L3.3@105.6,39.7
NetC3_1: C3.1 D2.2 L1.1 L4.2 TP3.1 | length 6.2
  Bottom Layer w2: 5.9,79.3 10.3,74.9
NetC10_1: C10.1 U1.2 | length 5.5
  Top Layer w0.5: C10.1@52.4,82 53.2,82 ; C10.1@52.425,82 53.2,82 ; U1.2@55.1,80.835 54.365,80.835 ; U1.2@55.9,80.835 54.365,80.835 ; 53.2,82 54.365,80.835
NetC12_1: C12.1 C16.1 C19.1 C28.2 R18.2 TP9.1 U1.7 U2.6 | length 152.3
  Top Layer w0.5: 58.8,82.097 58.975,84.1 C16.1@58.8,85.4 ; C12.1@58.8,83.706 58.975,85.8 C12.1@59,84.1 v1(60.2,84.1) C12.1@59.025,84.1 ; C16.1@59.2,85.8 C16.1@58.8,85.4 ; U1.7@60.7,80.835 59.365,80.835 ; v1(73.4,76.3) 77.5,76.3 79.1,77.9 83.5,77.9 ; U2.6@83.035,79.1 83.035,78.365 ; U2.6@83.035,79.9 83.035,78.365 ; 84.118,77.9 86.1,77.975 88.082,77.9 ; C19.1@113.467,131.726 111.375,132.1 ; C19.1@113.467,132.474 111.375,132.1 ; C19.1@113.533,131.726 115.625,132.1 C19.1@113.533,132.474 ; TP9.1@114.8,136.7 113.5,135.4 C19.1@113.5,132.1 ; 117.814,132.1 R18.2@119.8,132 119.7,132.1 C19.1@113.5,132.1 ; 58.8,81.4 C16.1@58.8,85.4 ; 58.8,81.4 U1.7@59.9,80.835 ; 58.8,81.4 59.365,80.835 ; 59.365,80.835 U1.7@59.9,80.835 ; 59.365,80.835 U1.7@59.9,80.835 ; 83.035,78.365 83.5,77.9 ; 83.5,77.9 88.7,77.9 89.9,76.7 94.3,76.7 96,78.4 96,79.7 102.7,86.4 106,92.9 110.8,97.7 110.8,132 110.9,132.1 C19.1@113.5,132.1 ; 111.375,132.1 C19.1@113.5,132.1
  Bottom Layer w0.5: v1(60.2,84.1) 61.5,84.1 69.3,76.3 v1(73.4,76.3)
NetC13_1: C13.1 R10.1 U1.5 | length 7
  Top Layer w0.5: U1.5@60.6,78.295 63.005,78.295 ; U1.5@61.4,78.295 63.005,78.295 ; R10.1@63.9,75.7 C13.1@63.9,77.4 63.005,78.295
NetC14_1: C14.1 R10.2 | length 3
  Top Layer w0.5: R10.2@65.5,75.7 C14.1@68.5,75.7
NetC15_1: C15.1 D4.1 R11.2 U1.3 | length 32.8
  Top Layer w0.5: D4.1@52.203,78.332 C15.1@52.375,80.3 ; C15.1@52.4,80.197 D4.1@52.2,78.3 D4.1@52.4,78.5 ; C15.1@52.425,80.3 53.135,79.565 ; 53.3,79.565 U1.3@55.1,79.565 ; U1.3@56.7,79.565 57.435,79.565 ; R11.2@56.814,75.787 57.7,77.996 ; R11.2@57,75.7 57.7,76.4 ; 57.305,75.549 57.7,76.4 ; R11.2@57.344,75.643 57.7,77.996 ; D4.1@52.4,78.5 C15.1@52.4,80.3 ; D4.1@52.4,78.5 C15.1@52.4,80.3 ; C15.1@52.4,80.3 53.135,79.565 ; 53.135,79.565 U1.3@55.9,79.565 57.435,79.565 ; R11.2@57.075,75.7 57.7,76.4 ; R11.2@57.075,75.7 57.7,77.996 ; R11.2@57.075,75.7 57.7,76.4 ; 57.435,79.565 57.7,79.3 57.7,76.4 ; 57.7,76.4 56.899,75.911 57.7,76.4
NetC17_1: C17.1 D5.1 K1.1 R13.2 | length 47.5
  Bottom Layer w0.5: C17.1@190.307,78.71 190.338,76.752 C17.1@190.338,78.71 ; D5.1@190.338,77.124 C17.1@190.3,79.1 190.338,79.062 D5.1@190.338,76.6 ; 192.297,76.55 D5.1@190.338,76.6 ; K1.1@192.342,69.223 193.3,71.801 ; K1.1@192.828,69.091 193.3,71.801 ; R13.2@192.853,76.179 193.3,74.074 ; R13.2@193.204,76.103 191.099,76.55 ; R13.2@193.222,76.899 191.099,76.55 ; R13.2@193.25,76.225 193.3,74.074 ; R13.2@193.25,76.5 191.099,76.55 ; R13.2@193.649,76.197 193.3,74.074 ; K1.1@193.824,69.101 193.3,71.801 ; K1.1@194.308,69.242 193.3,71.801 ; D5.1@190.338,76.6 190.388,76.55 193.3,76.55 193.3,69.077 K1.1@193.327,69.05 193.3,71.801
NetC21_2: C21.2 R28.2 | length 22.5
  Top Layer w1: R28.2@64.9,124.4 C21.2@68.75,124.4 ; R28.2@64.932,123.901 C21.2@68.75,124.4 ; R28.2@64.932,124.899 C21.2@68.75,124.4 ; R28.2@65.1,124.4 C21.2@68.75,124.4 ; R28.2@65.125,123.926 C21.2@68.75,124.4 ; R28.2@65.125,124.874 C21.2@68.75,124.4
NetC24_1: C24.1 Q3.1 R17.2 R19.2 | length 22.2
  Top Layer w0.5: R19.2@128.5,131.9 R19.2@128.553,131.847 ; R17.2@128.525,130.1 R19.2@128.553,131.847 ; Q3.1@128.553,126.3 R17.2@128.553,130.047 ; Q3.1@128.553,126.423 C24.1@128.5,128.4 128.553,126.525 C24.1@128.553,128.45 ; C24.1@128.553,128.122 R17.2@128.5,130.1 ; R17.2@128.5,130.1 128.525,128.4 R17.2@128.553,130.047 ; R17.2@128.5,130.1 128.525,131.9 R17.2@128.553,130.047 ; R17.2@128.5,130.1 R17.2@128.553,130.047 ; R17.2@128.553,130.047 R19.2@128.553,131.847
NetC25_1: C25.1 D9.1 R27.2 R38.2 | length 33.5
  Bottom Layer w0.5: R38.2@175.802,79.087 176.2,81.2 R38.2@176.598,79.087 ; R38.2@176.2,79.05 R27.2@176.2,85.5 D9.1@182.2,85.5 180.4,85.5 ; 176.2,83.5 R27.2@176.2,85.475 ; C25.1@178.469,85.996 R27.2@176.373,85.5 ; C25.1@178.506,85.2 R27.2@176.373,85.5 ; C25.1@178.525,85.6 R27.2@176.373,85.5 ; C25.1@179.075,85.6 181.228,85.5 ; C25.1@179.094,85.2 181.228,85.5 ; C25.1@179.131,85.996 181.228,85.5
NetC27_1: C27.1 R43.2 U2.2 U2.4 | length 29.8
  Top Layer w0.5: R43.2@65.6,82.5 66.733,82.5 69.7,79.533 69.7,78.6 73.3,75 77.7,75 79.5,73.2 81.7,73.2 ; U2.2@81.765,75.1 81.765,73.265 81.7,73.2 ; C27.1@84.3,70.8 84.305,70.805 84.305,72.605 ; U2.4@84.305,75.1 84.305,72.605 ; 81.7,73.2 82.562,72.338 84.038,72.338 84.305,72.605
NetD1_1: D1.1 D3.1 L1.2 Q1.2 Q6.2 R28.1
NetD5_2: D5.2 K1.2 Q5.3 | length 29.2
  Bottom Layer w0.5: K1.2@182.142,69.223 183.1,71.801 ; K1.2@182.628,69.091 183.1,71.801 ; 183.1,74.45 Q5.3@183.1,76.375 ; K1.2@183.624,69.101 183.1,71.801 ; K1.2@184.108,69.242 183.1,71.801 ; 185.105,76.6 D5.2@187.063,76.6 Q5.3@183.1,76.6 183.1,69.077 K1.2@183.127,69.05 183.1,71.801
NetD6_1: D6.1 D7.1 R20.2 R25.2 | length 263.1
  Top Layer w0.5: v1(85.8,71.6) 85.8,73.3 87.5,75 94.1,75 97.204,78.104 97.204,79.604 103.6,86 107.6,93.1 111.8,97.3 111.8,113.2 v1(116.7,118.1) ; R20.2@122.495,116.804 v1(121.1,117.2) ; R20.2@122.495,117.596 v1(121.1,117.2) ; v1(121.1,117.2) R20.2@122.55,117.2 v1(121.1,117.2)
  Top Layer w1: D7.1@29.35,59.05 29.35,62.75 ; 29.35,60.65 D6.1@29.35,64.35 ; D6.1@29.35,64.6 D7.1@29.35,58.8 ; D7.1@29.35,58.8 v1(31,58.7) 29.45,58.7 D7.1@29.35,58.8
  Bottom Layer w0.5: 85.8,53.7 v1(85.8,71.6) ; v1(116.7,118.1) 120.2,118.1 v1(121.1,117.2)
  Bottom Layer w1: v1(31,58.7) 35.8,58.7 40.8,53.7 85.8,53.7 129.1,53.7 136.2,60.8 172.3,60.8 R25.2@176.2,64.7 ; 173.429,61.929 R25.2@175.925,64.7
NetD8_2: D8.2 R23.2 | length 6.7
  Top Layer w0.5: D8.2@115.6,127.3 D8.2@115.5,127.4 117.433,127.7 ; 115.6,127.7 R23.2@118.2,127.7 ; 116.2,127.7 R23.2@118.175,127.7
NetD9_2: D9.2 Q5.1 R31.2 R39.2 | length 18.3
  Bottom Layer w0.5: Q5.1@182.147,78.8 182.2,78.853 R31.2@182.2,81.1 ; Q5.1@182.2,79.125 R31.2@182.2,81.1 ; R31.2@182.2,80.951 182.147,79.025 R31.2@182.2,80.952 ; R31.2@182.2,81.5 D9.2@182.2,83.3 ; D9.2@182.2,83.075 R31.2@182.2,81.1 ; R39.2@184.2,83.575 D9.2@182.2,83.3 ; R39.2@184.2,83.6 183.9,83.3 D9.2@182.2,83.3 ; R31.2@182.2,81.1 D9.2@182.2,83.3
NetD10_1: D10.1 R39.1 | length 6.5
  Bottom Layer w0.5: 184.1,86.1 D10.1@184.1,87.9 184.1,85.3 R39.1@184.2,85.2 ; 184.1,87.208 R39.1@184.2,85.225
NetD11_1: D11.1 R3.1 R44.1 U2.7 | length 53.4
  Top Layer w0.5: R3.1@75.5,80.34 75.752,78.196 ; R3.1@75.502,80.313 75.9,78.2 ; R3.1@75.515,80.243 75.9,79.604 ; R3.1@76.175,80.35 77.55,80.35 ; R3.1@76.233,79.954 77.55,80.35 ; R3.1@76.233,80.746 77.55,80.35 ; R3.1@76.285,80.243 75.9,79.604 ; R3.1@76.295,80.286 75.752,78.196 ; R3.1@76.298,80.313 75.9,78.2 ; R44.1@81.352,82.585 U2.7@81.765,80.475 ; R44.1@81.371,82.488 U2.7@81.765,80.7 ; R44.1@81.654,83.013 79.465,82.265 ; R44.1@81.751,82.5 U2.7@81.765,80.7 ; U2.7@81.765,79.9 R44.1@81.765,82.265 ; R44.1@81.778,82.226 79.465,82.265 ; R44.1@82.13,82.49 U2.7@81.765,80.7 ; R44.1@82.149,82.591 U2.7@81.765,80.475 ; 75.752,78.196 R3.1@75.9,80.35 ; 75.9,78.2 R3.1@75.9,80.35 ; 75.9,79.604 R3.1@75.9,80.35 ; 75.9,79.604 D11.1@75.7,77.7 75.9,77.9 R3.1@75.9,80.35 ; R3.1@75.9,80.35 77.55,80.35 ; 77.55,80.35 79.465,82.265 ; 79.465,82.265 R44.1@81.765,82.265 ; 79.465,82.265 81.75,82.625 U2.7@81.765,80.475 ; U2.7@81.765,80.7 R44.1@81.765,82.265
NetD11_2: D11.2 R24.1 | length 10
  Top Layer w0.5: R24.1@72.602,80.313 73,78.2 ; R24.1@73.398,80.313 73,78.2 ; 73,78.2 R24.1@73,80.35 73,78.2 ; 73,78.2 D11.2@73.5,77.7 73,78.2
NetD12_1: D12.1 R40.1 R44.2 U2.5 | length 13.2
  Top Layer w0.5: U2.5@84.305,79.9 R44.2@84.305,82.555 ; R44.2@84.513,82.762 R44.2@84.65,82.9 ; R44.2@84.65,82.625 86.975,82.625 89.25,80.35 R40.1@90.6,80.35 90.6,78.6 ; 90.6,78.6 D12.1@91.2,78 90.6,78.6
NetD12_2: D12.2 R41.1 | length 17
  Top Layer w0.5: R41.1@93.4,79.8 D12.2@93.4,78 R41.1@93.4,80.35 ; D12.2@93.4,78.2 R41.1@93.4,80.35 ; D12.2@93.4,78.2 93.002,80.313 D12.2@93.4,78.2 ; D12.2@93.4,78.2 93.798,80.313 D12.2@93.4,78.2 ; D12.2@93.4,78.2 R41.1@93.4,80.35
NetF1_2: F1.2 P1.1 TP1.1
NetJ3_1: J3.3 Q2.2 R13.1 R15.1 | length 175.9
  Top Layer w0.5: R15.1@123.8,126.1 123.8,128.047 Q2.2@124.053,128.3 124.65,128.897 124.65,132.85 v1(124.7,132.9) ; R15.1@123.8,126.112 Q2.2@124.053,128.075 ; R15.1@123.825,126.1 Q2.2@124.051,128.063
  Bottom Layer w0.5: v1(124.7,132.9) 126.64,134.84 J3.3@126.64,136.8 ; J3.3@126.62,136.8 126.62,138.22 127.2,138.8 133.1,138.8 134.9,137 205,137 212.9,129.1 212.9,85.9 203.5,76.5 R13.1@196.15,76.5 ; R13.1@196.187,76.102 198.3,76.5 R13.1@196.187,76.898
NetQ1_1: Q1.1 R1.1 R3.2 R24.2 TP7.1 | length 89.2
  Top Layer w0.5: TP7.1@62.8,85.7 65.025,83.475 66.307,83.475 66.532,83.25 R24.2@73,83.25 74,83.25 ; R24.2@73.312,82.852 75.425,83.25 R24.2@73.312,83.648 ; 73.337,84.277 R1.1@74.075,86.2 ; 73.592,84.239 R1.1@74.075,86.2 ; R24.2@73.664,83.157 R1.1@74.1,85.826 ; 73.839,84.225 R1.1@74.075,86.2 ; 74.1,84.225 R1.1@74.1,86.2 ; R1.1@74.125,86.2 76.1,86.2 ; R3.2@75.522,82.864 R24.2@73.487,83.615 ; R3.2@75.522,83.636 R24.2@73.487,82.885 ; R3.2@75.576,82.853 74,83.25 ; R3.2@75.576,83.647 74,83.25 ; R3.2@75.656,82.851 R24.2@73.487,82.885 ; R3.2@75.656,83.649 R24.2@73.487,83.615 ; R3.2@75.9,83.35 75.8,83.25 74,83.25 ; Q1.1@78.006,89.208 76.5,86.2 ; Q1.1@78.439,88.948 76.5,86.2 ; Q1.1@78.826,88.629 76.5,86.2 ; Q1.1@79,88.45 76.5,86.2 ; Q1.1@79,88.7 76.5,86.2 ; Q1.1@79.16,88.258 76.5,86.2 ; Q1.1@79.436,87.84 76.5,86.2 ; Q1.1@79.649,87.382 76.5,86.2 ; R24.2@73.385,82.866 74,83.25 ; R24.2@73.385,82.866 74,83.25 ; R24.2@73.385,82.866 74,83.25 ; R24.2@73.385,83.634 74,83.25 ; R24.2@73.385,83.634 74,83.25 ; R24.2@73.385,83.634 74,83.25 ; R24.2@73.487,82.885 R3.2@75.625,83.25 ; R24.2@73.487,83.615 R3.2@75.625,83.25 ; 74,83.25 R3.2@75.625,83.25 ; 74,83.25 74.1,83.35 ; 74.1,83.35 73.417,82.876 74.1,83.35 ; 74.1,83.35 73.324,83.647 74.1,83.35 ; 74.1,83.35 R1.1@74.1,86.2 ; R1.1@74.1,86.2 76.5,86.2
NetQ2_1: Q2.1 R15.2 R16.2 | length 13.6
  Top Layer w0.5: Q2.1@122.147,128.3 122.3,128.147 R16.2@122.3,124.3 R15.2@122.225,126.1 ; R15.2@122.175,126.1 122.147,128.075 R15.2@122.3,126.134 ; R16.2@122.275,124.3 R15.2@122.225,126.1 ; Q2.1@122.3,128.081 R15.2@122.225,126.1
NetQ2_3: Q2.3 R18.1 | length 7.3
  Top Layer w0.5: R18.1@119.8,130.4 119.9,130.5 Q2.3@123.1,130.5 121.175,130.5 ; R18.1@119.8,130.425 121.785,130.5
NetQ3_3: Q3.3 R16.1 | length 7.9
  Top Layer w0.5: R16.1@123.9,124.3 124.2,124 127.5,124 Q3.3@127.6,124.1 125.663,124 ; R16.1@123.925,124.3 126.027,124
NetQ4_2: Q4.2 R14.1 | length 6.2
  Top Layer w0.5: R14.1@115.5,121.4 117.247,121.4 ; R14.1@115.697,121.4 Q4.2@117.847,122 117.247,121.4 ; 117.247,121.4 117.847,121.775 117.247,121.4
NetQ6_1: Q6.1 R40.2 R41.2 R42.1 TP4.1 | length 138.7
  Top Layer w0.5: R40.2@90.6,83.25 R41.2@93.4,83.25 93.4,86.1 93.5,86.2 ; R40.2@90.841,82.851 R41.2@93.009,82.867 ; R40.2@90.841,83.649 R41.2@93.009,83.633 ; R40.2@90.982,82.865 R41.2@93.009,83.633 ; R40.2@90.982,83.635 R41.2@93.009,82.867 ; R42.1@92.9,86.2 93.5,86.2 ; R41.2@93.002,83.287 93.4,85.4 R41.2@93.798,83.287 ; R41.2@93.088,82.852 R40.2@90.975,83.25 ; R41.2@93.088,83.648 R40.2@90.975,83.25 ; R41.2@93.125,83.25 R40.2@90.975,83.25 ; 93.4,84.037 R42.1@92.925,86.2 ; 94.9,86.2 R42.1@92.925,86.2 ; Q6.1@96.506,89.208 95,86.2 ; Q6.1@96.939,88.948 95,86.2 ; Q6.1@97.326,88.629 95,86.2 ; Q6.1@97.5,88.45 95,86.2 ; Q6.1@97.5,88.7 95,86.2 ; Q6.1@97.66,88.258 95,86.2 ; Q6.1@97.936,87.84 95,86.2 ; Q6.1@98.149,87.382 95,86.2 ; R40.2@90.875,83.25 R41.2@93.009,82.867 ; R40.2@90.875,83.25 R41.2@93.025,83.25 ; R40.2@90.875,83.25 R41.2@93.009,83.633 ; R40.2@90.875,83.25 R41.2@93.025,83.25 ; R42.1@92.925,86.2 93.5,86.2 ; R42.1@92.925,86.2 93.5,86.2 ; R42.1@92.925,86.2 93.5,86.2 ; R41.2@93.025,83.25 90.912,82.852 R41.2@93.025,83.25 ; R41.2@93.025,83.25 90.912,83.648 R41.2@93.025,83.25 ; 93.5,86.2 95,86.2
  Bottom Layer w1: TP4.1@99.522,92.093 Q6.1@98.272,88.314 ; TP4.1@99.574,92.191 Q6.1@97.5,88.7 ; TP4.1@99.585,92.207 Q6.1@97.5,88.95 ; TP4.1@99.677,92.303 Q6.1@96.949,89.784 ; TP4.1@100.264,91.457 Q6.1@96.949,89.784 ; TP4.1@100.371,91.541 Q6.1@97.5,88.95 ; TP4.1@100.386,91.557 Q6.1@97.5,88.7 ; TP4.1@100.449,91.646 Q6.1@98.272,88.314 ; Q6.1@96.949,89.784 TP4.1@100,91.9 ; Q6.1@96.949,89.784 TP4.1@100,91.2 ; Q6.1@97.5,88.7 TP4.1@100,91.9 ; Q6.1@97.5,88.7 TP4.1@100,91.2 ; Q6.1@97.5,88.95 TP4.1@100,91.9 ; Q6.1@97.5,88.95 TP4.1@100,91.2 ; Q6.1@98.272,88.314 TP4.1@100,91.9 ; Q6.1@98.272,88.314 TP4.1@100,91.2 ; TP4.1@100,91.2 TP4.1@100,91.9
NetR6_1: R6.1 R7.2 | length 32.6
  Top Layer w0.5: R7.2@126.821,112.101 R6.1@128.982,112.145 ; R7.2@126.821,112.899 R6.1@128.982,112.855 ; R7.2@126.952,112.113 R6.1@128.982,112.855 ; R7.2@126.952,112.887 R6.1@128.982,112.145 ; R6.1@129.213,112.102 R7.2@127.1,112.5 ; R6.1@129.213,112.898 R7.2@127.1,112.5 ; R7.2@126.85,112.5 R6.1@129,112.5 ; R7.2@126.85,112.5 R6.1@128.982,112.855 ; R7.2@126.85,112.5 R6.1@128.982,112.145 ; R7.2@126.85,112.5 R6.1@129.25,112.5 R7.2@127.1,112.5 ; R6.1@129,112.5 126.887,112.102 R6.1@129,112.5 ; R6.1@129,112.5 126.887,112.898 R6.1@129,112.5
